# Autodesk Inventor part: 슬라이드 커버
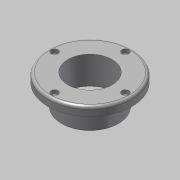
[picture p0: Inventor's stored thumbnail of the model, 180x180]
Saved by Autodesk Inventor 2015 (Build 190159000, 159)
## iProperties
Created: 2015-10
Part Number: 슬라이드 커버
Document SubType Name: Modeling
Designer: mdu
Density: 7.86 g/cm^3
Material: 강철, 연강
Mass: 598.523 g
Surface Area: 229.996 cm^2
Volume: 76.148 cm^3
Appearance: 강철
Author: mdu
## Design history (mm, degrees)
sketch "스케치1"
  geometry: C1 r 47.5 at (0, 0); C2 r 32.5 at (0, 0); 1 further point
  constraints: 2 centre point, 2 coincident
  dimensions: "d33" = 95 diameter of C1; "d35" = 65 diameter of C2
extrude "돌출1" new body sketch "스케치1" distance "d0" = 10; taper "d1" = 0 deg
extrude "돌출2" join sketch "스케치1" distance "d2" = 25; taper "d3" = 0 deg
hole "구멍1" diameter "d6" = 50; stored, may be unused: countersink angle "d10" = 90 deg, drill point angle "d12" = 118 deg; dims "d4" = 10, "d5" = 10, "d7" = 6, "d8" = 4, "d9" = 2, "d11" = 8
sketch "스케치2" dims "d36" = 80
  geometry: 4 further points
  constraints: 2 coincident, 2 vertical alignment, 2 other
hole "구멍2" sketch "스케치2" at (0, 40) diameter "d13" = 4.5; stored, may be unused: countersink angle "d17" = 90 deg, drill point angle "d19" = 118 deg; dims "d14" = 6, "d15" = 8, "d16" = 4.4, "d18" = 8
fillet "모깎기1" dims "d23" = 3
chamfer "모따기1" distance "d24" = 1; stored, may be unused: second distance "d25" = 2, angle "d26" = 45 deg
sketch "스케치3"
  geometry: C1 r 25 at (0, 0); C2 r 30 at (0, 0); C3 r 26 at (0, 0) reference; 1 further point
  constraints: 2 centre point, 2 coincident
  dimensions: "d27" = 60 diameter of C2
extrude "돌출3" cut sketch "스케치3" distance "d28" = 3; taper "d29" = 0 deg
chamfer "모따기2" distance "d30" = 1; stored, may be unused: second distance "d31" = 2, angle "d32" = 45 deg
node "솔리드1"
pattern_circular "원형 패턴1" dims angle "d21" = 360 deg
